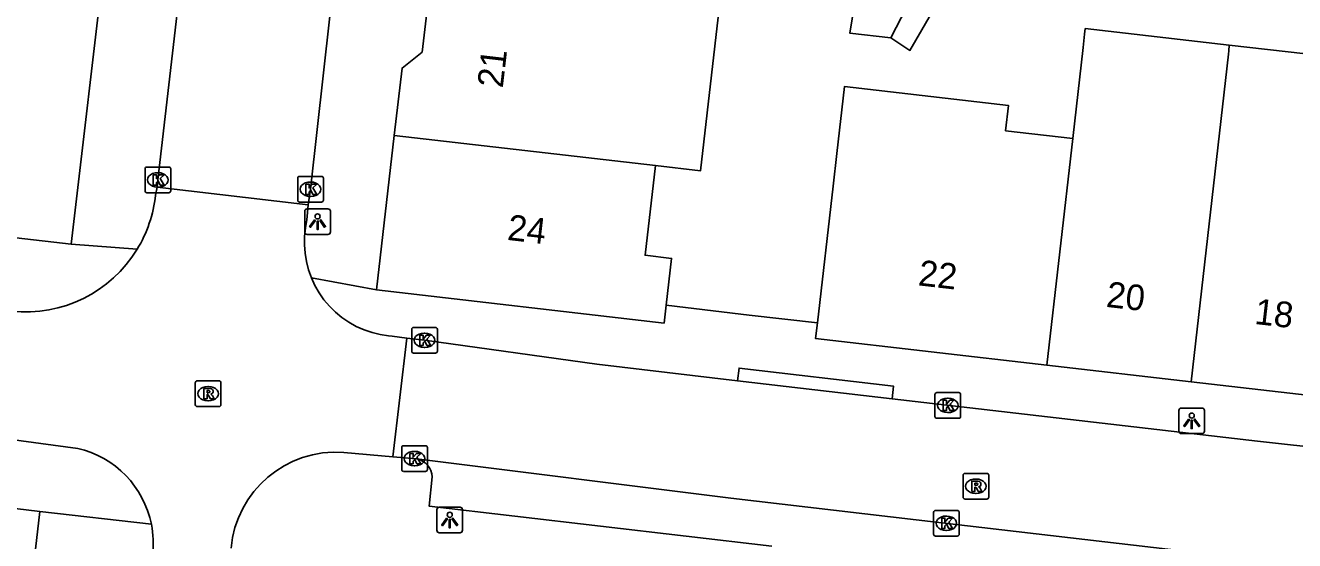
# Model space of a CAD drawing. Extents: x 161696 to 162377, y 380761 to 381673.
# Drawn here: x 162152.75 to 162202.16, y 381134.62 to 381154.7 of the extents above; entities that cross this region are included whole.
import ezdxf

# ---------------------------------------------------------------- set-up
doc = ezdxf.new("R2010")
doc.units = 0
for name, color, linetype in [('IMGEO_Kolk', 7, 'Continuous'), ('IMGEO_Lichtpunt', 7, 'Continuous'), ('IMGEO_Muur', 7, 'Continuous'), ('IMGEO_Pand', 7, 'Continuous'), ('IMGEO_Pand_nummerreeks', 7, 'Continuous'), ('IMGEO_Rijbaan_lokaal_open', 7, 'Continuous'), ('IMGEO_Rioolput', 7, 'Continuous'), ('IMGEO_Voetpad_open', 7, 'Continuous')]:
    doc.layers.add(name, color=color, linetype=linetype)

msp = doc.modelspace()

# ---------------------------------------------------------------- linework, layer by layer
at = {"layer": 'IMGEO_Kolk'}
for p, q in [((162157.405, 381148.25), (162157.405, 381149.102)), ((162157.48, 381149.176), (162158.332, 381149.176)), ((162157.893, 381148.956), (162157.918, 381148.956)), ((162158.406, 381149.102), (162158.406, 381148.25)), ((162163.424, 381148.812), (162164.276, 381148.812)), ((162157.916, 381148.396), (162157.891, 381148.396)), ((162163.349, 381147.886), (162163.349, 381148.738)), ((162163.837, 381148.592), (162163.862, 381148.592)), ((162164.35, 381148.738), (162164.35, 381147.886)), ((162158.332, 381148.176), (162157.48, 381148.176)), ((162164.276, 381147.812), (162163.424, 381147.812)), ((162163.86, 381148.032), (162163.835, 381148.032)), ((162167.787, 381142.001), (162167.787, 381142.853)), ((162167.862, 381142.927), (162168.714, 381142.927)), ((162168.788, 381142.853), (162168.788, 381142.001)), ((162168.275, 381142.707), (162168.3, 381142.707)), ((162168.714, 381141.927), (162167.862, 381141.927)), ((162168.298, 381142.147), (162168.273, 381142.147)), ((162188.234, 381140.39), (162189.086, 381140.39)), ((162188.159, 381139.464), (162188.159, 381140.316)), ((162188.647, 381140.17), (162188.672, 381140.17)), ((162189.16, 381140.316), (162189.16, 381139.464)), ((162189.086, 381139.39), (162188.234, 381139.39)), ((162188.67, 381139.61), (162188.645, 381139.61)), ((162167.399, 381137.393), (162167.399, 381138.245)), ((162167.474, 381138.319), (162168.326, 381138.319)), ((162167.887, 381138.099), (162167.912, 381138.099)), ((162168.4, 381138.245), (162168.4, 381137.393)), ((162167.91, 381137.539), (162167.885, 381137.539)), ((162168.326, 381137.319), (162167.474, 381137.319)), ((162188.103, 381134.872), (162188.103, 381135.724)), ((162188.178, 381135.798), (162189.03, 381135.798)), ((162188.591, 381135.578), (162188.616, 381135.578)), ((162189.104, 381135.724), (162189.104, 381134.872)), ((162188.614, 381135.018), (162188.589, 381135.018)), ((162189.03, 381134.798), (162188.178, 381134.798))]:
    msp.add_line(p, q, dxfattribs=at)
for points in [[(162157.405, 381148.25), (162157.405, 381149.102)], [(162157.48, 381149.176), (162158.332, 381149.176)], [(162157.726, 381148.876), (162157.849, 381148.876), (162157.849, 381148.725), (162157.979, 381148.876), (162158.143, 381148.876), (162157.997, 381148.725), (162158.15, 381148.476), (162157.998, 381148.476), (162157.913, 381148.64), (162157.849, 381148.573), (162157.849, 381148.476), (162157.726, 381148.476), (162157.726, 381148.876)], [(162158.406, 381149.102), (162158.406, 381148.25)], [(162163.424, 381148.812), (162164.276, 381148.812)], [(162163.349, 381147.886), (162163.349, 381148.738)], [(162163.67, 381148.512), (162163.793, 381148.512), (162163.793, 381148.361), (162163.923, 381148.512), (162164.087, 381148.512), (162163.941, 381148.361), (162164.094, 381148.112), (162163.942, 381148.112), (162163.857, 381148.276), (162163.793, 381148.209), (162163.793, 381148.112), (162163.67, 381148.112), (162163.67, 381148.512)], [(162164.35, 381148.738), (162164.35, 381147.886)], [(162158.332, 381148.176), (162157.48, 381148.176)], [(162164.276, 381147.812), (162163.424, 381147.812)], [(162167.787, 381142.001), (162167.787, 381142.853)], [(162167.862, 381142.927), (162168.714, 381142.927)], [(162168.788, 381142.853), (162168.788, 381142.001)], [(162168.108, 381142.627), (162168.231, 381142.627), (162168.231, 381142.476), (162168.361, 381142.627), (162168.525, 381142.627), (162168.379, 381142.476), (162168.532, 381142.227), (162168.38, 381142.227), (162168.295, 381142.391), (162168.231, 381142.324), (162168.231, 381142.227), (162168.108, 381142.227), (162168.108, 381142.627)], [(162168.714, 381141.927), (162167.862, 381141.927)], [(162188.234, 381140.39), (162189.086, 381140.39)], [(162188.159, 381139.464), (162188.159, 381140.316)], [(162188.48, 381140.09), (162188.603, 381140.09), (162188.603, 381139.939), (162188.733, 381140.09), (162188.897, 381140.09), (162188.751, 381139.939), (162188.904, 381139.69), (162188.752, 381139.69), (162188.667, 381139.854), (162188.603, 381139.787), (162188.603, 381139.69), (162188.48, 381139.69), (162188.48, 381140.09)], [(162189.16, 381140.316), (162189.16, 381139.464)], [(162189.086, 381139.39), (162188.234, 381139.39)], [(162167.399, 381137.393), (162167.399, 381138.245)], [(162167.474, 381138.319), (162168.326, 381138.319)], [(162167.72, 381138.019), (162167.843, 381138.019), (162167.843, 381137.868), (162167.973, 381138.019), (162168.137, 381138.019), (162167.991, 381137.868), (162168.144, 381137.619), (162167.992, 381137.619), (162167.907, 381137.783), (162167.843, 381137.716), (162167.843, 381137.619), (162167.72, 381137.619), (162167.72, 381138.019)], [(162168.4, 381138.245), (162168.4, 381137.393)], [(162168.326, 381137.319), (162167.474, 381137.319)], [(162188.103, 381134.872), (162188.103, 381135.724)], [(162188.178, 381135.798), (162189.03, 381135.798)], [(162188.424, 381135.498), (162188.547, 381135.498), (162188.547, 381135.347), (162188.677, 381135.498), (162188.841, 381135.498), (162188.695, 381135.347), (162188.848, 381135.098), (162188.696, 381135.098), (162188.611, 381135.262), (162188.547, 381135.195), (162188.547, 381135.098), (162188.424, 381135.098), (162188.424, 381135.498)], [(162189.104, 381135.724), (162189.104, 381134.872)], [(162189.03, 381134.798), (162188.178, 381134.798)]]:
    msp.add_lwpolyline(points, dxfattribs=at)
for centre, start, end in [((162157.482, 381149.1), 91.552, 178.448), ((162157.482, 381149.1), 91.552, 178.448), ((162158.33, 381149.1), 1.552, 88.448), ((162158.33, 381149.1), 1.552, 88.448), ((162163.426, 381148.736), 91.552, 178.448), ((162163.426, 381148.736), 91.552, 178.448), ((162164.274, 381148.736), 1.552, 88.448), ((162164.274, 381148.736), 1.552, 88.448), ((162157.482, 381148.252), 181.552, 268.448), ((162157.482, 381148.252), 181.552, 268.448), ((162158.33, 381148.252), 271.552, 358.448), ((162158.33, 381148.252), 271.552, 358.448), ((162163.426, 381147.888), 181.552, 268.448), ((162163.426, 381147.888), 181.552, 268.448), ((162164.274, 381147.888), 271.552, 358.448), ((162164.274, 381147.888), 271.552, 358.448), ((162167.864, 381142.851), 91.552, 178.448), ((162167.864, 381142.851), 91.552, 178.448), ((162168.712, 381142.851), 1.552, 88.448), ((162168.712, 381142.851), 1.552, 88.448), ((162167.864, 381142.003), 181.552, 268.448), ((162167.864, 381142.003), 181.552, 268.448), ((162168.712, 381142.003), 271.552, 358.448), ((162168.712, 381142.003), 271.552, 358.448), ((162188.236, 381140.314), 91.552, 178.448), ((162188.236, 381140.314), 91.552, 178.448), ((162189.084, 381140.314), 1.552, 88.448), ((162189.084, 381140.314), 1.552, 88.448), ((162188.236, 381139.466), 181.552, 268.448), ((162188.236, 381139.466), 181.552, 268.448), ((162189.084, 381139.466), 271.552, 358.448), ((162189.084, 381139.466), 271.552, 358.448), ((162167.476, 381138.243), 91.552, 178.448), ((162167.476, 381138.243), 91.552, 178.448), ((162168.324, 381138.243), 1.552, 88.448), ((162168.324, 381138.243), 1.552, 88.448), ((162167.476, 381137.395), 181.552, 268.448), ((162167.476, 381137.395), 181.552, 268.448), ((162168.324, 381137.395), 271.552, 358.448), ((162168.324, 381137.395), 271.552, 358.448), ((162188.18, 381135.722), 91.552, 178.448), ((162188.18, 381135.722), 91.552, 178.448), ((162189.028, 381135.722), 1.552, 88.448), ((162189.028, 381135.722), 1.552, 88.448), ((162188.18, 381134.874), 181.552, 268.448), ((162188.18, 381134.874), 181.552, 268.448), ((162189.028, 381134.874), 271.552, 358.448), ((162189.028, 381134.874), 271.552, 358.448)]:
    msp.add_arc(centre, 0.0765, start, end, dxfattribs=at)
for centre, major_axis, ratio, start_param, end_param in [((162157.892, 381148.676), (-0.387, 0.002), 0.722429, 4.712389, 7.853982), ((162157.917, 381148.676), (-0.39, 0.002), 0.717154, 1.570796, 4.712389), ((162163.836, 381148.312), (-0.387, 0.002), 0.722429, 4.712389, 7.853982), ((162163.861, 381148.312), (-0.39, 0.002), 0.717154, 1.570796, 4.712389), ((162168.274, 381142.427), (-0.387, 0.002), 0.722429, 4.712389, 7.853982), ((162168.299, 381142.427), (-0.39, 0.002), 0.717154, 1.570796, 4.712389), ((162188.646, 381139.89), (-0.387, 0.002), 0.722429, 4.712389, 7.853982), ((162188.671, 381139.89), (-0.39, 0.002), 0.717154, 1.570796, 4.712389), ((162167.886, 381137.819), (-0.387, 0.002), 0.722429, 4.712389, 7.853982), ((162167.911, 381137.819), (-0.39, 0.002), 0.717154, 1.570796, 4.712389), ((162188.59, 381135.298), (-0.387, 0.002), 0.722429, 4.712389, 7.853982), ((162188.615, 381135.298), (-0.39, 0.002), 0.717154, 1.570796, 4.712389)]:
    msp.add_ellipse(centre, major_axis=major_axis, ratio=ratio, start_param=start_param, end_param=end_param, dxfattribs=at)
at = {"layer": 'IMGEO_Lichtpunt'}
for p, q in [((162163.625, 381147.454), (162163.625, 381146.647)), ((162163.625, 381147.454), (162163.625, 381146.647)), ((162164.527, 381147.549), (162163.719, 381147.549)), ((162164.527, 381147.549), (162163.719, 381147.549)), ((162164.621, 381146.647), (162164.621, 381147.454)), ((162164.621, 381146.647), (162164.621, 381147.454)), ((162163.719, 381146.553), (162164.527, 381146.553)), ((162163.719, 381146.553), (162164.527, 381146.553)), ((162197.658, 381139.693), (162197.658, 381138.886)), ((162197.658, 381139.693), (162197.658, 381138.886)), ((162198.56, 381139.788), (162197.752, 381139.788)), ((162198.56, 381139.788), (162197.752, 381139.788)), ((162198.654, 381138.886), (162198.654, 381139.693)), ((162198.654, 381138.886), (162198.654, 381139.693)), ((162197.752, 381138.792), (162198.56, 381138.792)), ((162197.752, 381138.792), (162198.56, 381138.792)), ((162169.669, 381135.925), (162168.861, 381135.925)), ((162169.669, 381135.925), (162168.861, 381135.925)), ((162168.767, 381135.83), (162168.767, 381135.023)), ((162168.767, 381135.83), (162168.767, 381135.023)), ((162169.763, 381135.023), (162169.763, 381135.83)), ((162169.763, 381135.023), (162169.763, 381135.83)), ((162168.861, 381134.929), (162169.669, 381134.929)), ((162168.861, 381134.929), (162169.669, 381134.929))]:
    msp.add_line(p, q, dxfattribs=at)
for points in [[(162163.999, 381147.118), (162164.038, 381147.09), (162163.85, 381146.828), (162163.812, 381146.855), (162163.999, 381147.118)], [(162164.101, 381147.07), (162164.148, 381147.07), (162164.148, 381146.748), (162164.101, 381146.748), (162164.101, 381147.07)], [(162164.211, 381147.09), (162164.249, 381147.117), (162164.436, 381146.855), (162164.397, 381146.827), (162164.211, 381147.09)], [(162198.032, 381139.357), (162198.071, 381139.329), (162197.883, 381139.067), (162197.845, 381139.094), (162198.032, 381139.357)], [(162198.134, 381139.309), (162198.181, 381139.309), (162198.181, 381138.987), (162198.134, 381138.987), (162198.134, 381139.309)], [(162198.244, 381139.329), (162198.282, 381139.356), (162198.469, 381139.094), (162198.43, 381139.066), (162198.244, 381139.329)], [(162169.141, 381135.494), (162169.18, 381135.466), (162168.992, 381135.204), (162168.954, 381135.231), (162169.141, 381135.494)], [(162169.243, 381135.446), (162169.29, 381135.446), (162169.29, 381135.124), (162169.243, 381135.124), (162169.243, 381135.446)], [(162169.353, 381135.466), (162169.391, 381135.493), (162169.578, 381135.231), (162169.539, 381135.203), (162169.353, 381135.466)]]:
    msp.add_lwpolyline(points, dxfattribs=at)
for centre in [(162164.124, 381147.252), (162198.157, 381139.491), (162169.266, 381135.628)]:
    msp.add_circle(centre, 0.0994, dxfattribs=at)
for centre, start, end in [((162163.719, 381147.454), 90, 180), ((162163.719, 381147.454), 90, 180), ((162164.527, 381147.454), 0, 90), ((162164.527, 381147.454), 0, 90), ((162163.719, 381146.647), 180, 270), ((162163.719, 381146.647), 180, 270), ((162164.527, 381146.647), 270, 0), ((162164.527, 381146.647), 270, 360), ((162197.752, 381139.693), 90, 180), ((162197.752, 381139.693), 90, 180), ((162198.56, 381139.693), 0, 90), ((162198.56, 381139.693), 0, 90), ((162197.752, 381138.886), 180, 270), ((162197.752, 381138.886), 180, 270), ((162198.56, 381138.886), 270, 0), ((162198.56, 381138.886), 270, 360), ((162168.861, 381135.83), 90, 180), ((162168.861, 381135.83), 90, 180), ((162169.669, 381135.83), 0, 90), ((162169.669, 381135.83), 0, 90), ((162168.861, 381135.023), 180, 270), ((162168.861, 381135.023), 180, 270), ((162169.669, 381135.023), 270, 0), ((162169.669, 381135.023), 270, 360)]:
    msp.add_arc(centre, 0.0946, start, end, dxfattribs=at)
at = {"layer": 'IMGEO_Muur'}
msp.add_lwpolyline([(162177.694, 381143.796), (162180.605, 381143.446)], dxfattribs=at)
at = {"layer": 'IMGEO_Pand'}
for points in [[(162186.438, 381154.204), (162184.851, 381154.388), (162185.377, 381157.678), (162188.067, 381157.367)], [(162188.067, 381157.367), (162186.438, 381154.204)], [(162167.107, 381150.404), (162167.412, 381153.033), (162168.194, 381153.652), (162168.502, 381156.312)], [(162179.724, 381155.017), (162179.03, 381149.027), (162177.278, 381149.23)], [(162193.523, 381150.286), (162193.925, 381153.829), (162193.985, 381154.352), (162194.01, 381154.57), (162199.62, 381153.925)], [(162198.134, 381140.811), (162199.583, 381153.573), (162199.597, 381153.707), (162199.62, 381153.925)], [(162199.62, 381153.925), (162202.606, 381153.582), (162203.142, 381154.11), (162204.868, 381153.912), (162204.933, 381153.739), (162205.168, 381153.112)], [(162183.584, 381143.104), (162184.191, 381148.432), (162184.336, 381149.703), (162184.634, 381152.312), (162191.022, 381151.577), (162190.91, 381150.587), (162193.523, 381150.286)], [(162166.411, 381144.391), (162167.107, 381150.404)], [(162167.107, 381150.404), (162177.278, 381149.23)], [(162193.523, 381150.286), (162192.52, 381141.456)], [(162177.278, 381149.23), (162176.873, 381145.737), (162177.905, 381145.618), (162177.694, 381143.796)], [(162177.694, 381143.796), (162177.613, 381143.094), (162166.411, 381144.391)], [(162192.52, 381141.456), (162183.513, 381142.49), (162183.584, 381143.104)], [(162198.134, 381140.811), (162192.52, 381141.456)], [(162203.896, 381140.149), (162198.134, 381140.811)]]:
    msp.add_lwpolyline(points, dxfattribs=at)
at = {"layer": 'IMGEO_Rijbaan_lokaal_open'}
for points in [[(162157.877, 381148.391), (162157.908, 381148.676), (162159.365, 381161.363), (162161.049, 381175.536), (162162.665, 381189.882)], [(162167.521, 381180.59), (162165.836, 381166.11), (162163.848, 381148.312), (162163.756, 381147.701)], [(162157.811, 381148.076), (162157.877, 381148.391)], [(162163.756, 381147.701), (162157.877, 381148.391)], [(162163.756, 381147.701), (162163.71, 381147.125), (162163.647, 381146.802), (162163.613, 381146.474), (162163.608, 381146.145), (162163.633, 381145.816), (162163.687, 381145.491), (162163.769, 381145.173), (162163.88, 381144.862)], [(162163.88, 381144.862), (162164.018, 381144.563), (162164.183, 381144.278), (162164.372, 381144.008), (162164.584, 381143.757), (162164.819, 381143.525), (162165.072, 381143.315), (162165.344, 381143.129), (162165.631, 381142.968), (162165.932, 381142.833), (162166.243, 381142.725), (162166.563, 381142.646), (162166.888, 381142.595), (162167.021, 381142.583), (162167.592, 381142.51)], [(162167.053, 381137.885), (162167.592, 381142.51)], [(162167.592, 381142.51), (162168.285, 381142.426), (162174.995, 381141.497), (162180.474, 381140.85)], [(162186.489, 381140.14), (162180.474, 381140.85)], [(162186.489, 381140.14), (162200.716, 381138.494), (162203.646, 381138.166), (162217.018, 381136.75), (162220.241, 381136.371)], [(162151.612, 381138.643), (162154.785, 381138.216)], [(162165.142, 381138.059), (162167.053, 381137.885)], [(162167.974, 381137.811), (162167.053, 381137.885)], [(162219.35, 381131.833), (162212.969, 381132.576), (162202.92, 381133.625), (162201.233, 381133.817), (162189.43, 381135.203), (162180.206, 381136.281), (162167.974, 381137.811)]]:
    msp.add_lwpolyline(points, dxfattribs=at)
for centre, radius, start, end in [((162152.776, 381148.61), 5.063, 328.5832, 353.9437), ((162152.754, 381148.616), 5.085, 263.9214, 328.6629), ((162153.918, 381134.508), 3.808, 11.3713, 76.838), ((162164.846, 381133.959), 4.111, 85.865, 174.8588), ((162153.939, 381134.506), 3.787, 353.4744, 11.4626)]:
    msp.add_arc(centre, radius, start, end, dxfattribs=at)
at = {"layer": 'IMGEO_Rioolput'}
for p, q in [((162159.36, 381139.921), (162159.36, 381140.773)), ((162159.435, 381140.847), (162160.287, 381140.847)), ((162159.848, 381140.627), (162159.873, 381140.627)), ((162160.361, 381140.773), (162160.361, 381139.921)), ((162159.871, 381140.067), (162159.846, 381140.067)), ((162160.287, 381139.847), (162159.435, 381139.847)), ((162189.255, 381136.315), (162189.255, 381137.167)), ((162189.33, 381137.241), (162190.182, 381137.241)), ((162189.743, 381137.021), (162189.768, 381137.021)), ((162190.256, 381137.167), (162190.256, 381136.315)), ((162189.766, 381136.461), (162189.741, 381136.461)), ((162190.182, 381136.241), (162189.33, 381136.241))]:
    msp.add_line(p, q, dxfattribs=at)
for points in [[(162159.36, 381139.921), (162159.36, 381140.773)], [(162159.435, 381140.847), (162160.287, 381140.847)], [(162159.949, 381140.545), (162159.697, 381140.547), (162159.697, 381140.147)], [(162159.875, 381140.466), (162159.821, 381140.466), (162159.821, 381140.385)], [(162159.821, 381140.385), (162159.873, 381140.385)], [(162160.361, 381140.773), (162160.361, 381139.921)], [(162159.697, 381140.147), (162159.821, 381140.147), (162159.821, 381140.309), (162159.832, 381140.309)], [(162159.879, 381140.28), (162159.95, 381140.147), (162160.09, 381140.147), (162160.025, 381140.273)], [(162160.287, 381139.847), (162159.435, 381139.847)], [(162189.255, 381136.315), (162189.255, 381137.167)], [(162189.33, 381137.241), (162190.182, 381137.241)], [(162189.844, 381136.939), (162189.592, 381136.941), (162189.592, 381136.541)], [(162190.256, 381137.167), (162190.256, 381136.315)], [(162189.592, 381136.541), (162189.716, 381136.541), (162189.716, 381136.703), (162189.727, 381136.703)], [(162189.77, 381136.86), (162189.716, 381136.86), (162189.716, 381136.779)], [(162189.716, 381136.779), (162189.768, 381136.779)], [(162189.774, 381136.674), (162189.845, 381136.541), (162189.985, 381136.541), (162189.92, 381136.667)], [(162190.182, 381136.241), (162189.33, 381136.241)]]:
    msp.add_lwpolyline(points, dxfattribs=at)
for centre, radius, start, end in [((162159.437, 381140.771), 0.0765, 91.552, 178.448), ((162159.437, 381140.771), 0.0765, 91.552, 178.448), ((162159.857, 381140.574), 0.19, 274.7715, 282.9687), ((162159.881, 381140.37), 0.0964, 77.0061, 93.1865), ((162159.895, 381140.427), 0.0378, 276.6634, 79.6772), ((162159.948, 381140.435), 0.109, 350.3612, 89.416), ((162159.946, 381140.435), 0.112, 277.5842, 350.9817), ((162160.285, 381140.771), 0.0765, 1.552, 88.448), ((162160.285, 381140.771), 0.0765, 1.552, 88.448), ((162159.437, 381139.923), 0.0765, 181.552, 268.448), ((162159.437, 381139.923), 0.0765, 181.552, 268.448), ((162159.831, 381140.256), 0.0533, 26.0293, 88.6989), ((162159.93, 381140.22), 0.108, 29.5134, 73.7905), ((162160.285, 381139.923), 0.0765, 271.552, 358.448), ((162160.285, 381139.923), 0.0765, 271.552, 358.448), ((162189.332, 381137.165), 0.0765, 91.552, 178.448), ((162189.332, 381137.165), 0.0765, 91.552, 178.448), ((162189.843, 381136.829), 0.109, 350.3612, 89.416), ((162190.18, 381137.165), 0.0765, 1.552, 88.448), ((162190.18, 381137.165), 0.0765, 1.552, 88.448), ((162189.726, 381136.65), 0.0533, 26.0293, 88.6989), ((162189.752, 381136.968), 0.19, 274.7715, 282.9687), ((162189.776, 381136.764), 0.0964, 77.0061, 93.1865), ((162189.79, 381136.821), 0.0378, 276.6634, 79.6772), ((162189.841, 381136.829), 0.112, 277.5842, 350.9817), ((162189.825, 381136.614), 0.108, 29.5134, 73.7905), ((162189.332, 381136.317), 0.0765, 181.552, 268.448), ((162189.332, 381136.317), 0.0765, 181.552, 268.448), ((162190.18, 381136.317), 0.0765, 271.552, 358.448), ((162190.18, 381136.317), 0.0765, 271.552, 358.448)]:
    msp.add_arc(centre, radius, start, end, dxfattribs=at)
for centre, major_axis, ratio, start_param, end_param in [((162159.847, 381140.347), (-0.387, 0.002), 0.722429, 4.712389, 7.853982), ((162159.872, 381140.347), (-0.39, 0.002), 0.717154, 1.570796, 4.712389), ((162189.742, 381136.741), (-0.387, 0.002), 0.722429, 4.712389, 7.853982), ((162189.767, 381136.741), (-0.39, 0.002), 0.717154, 1.570796, 4.712389)]:
    msp.add_ellipse(centre, major_axis=major_axis, ratio=ratio, start_param=start_param, end_param=end_param, dxfattribs=at)
at = {"layer": 'IMGEO_Voetpad_open'}
for points in [[(162199.213, 381203.105), (162194.213, 381159.563), (162190.787, 381159.956), (162187.187, 381153.72), (162186.438, 381154.204)], [(162154.533, 381146.175), (162155.871, 381157.555)], [(162105.038, 381151.871), (162154.533, 381146.175)], [(162154.533, 381146.175), (162157.097, 381145.971)], [(162166.411, 381144.391), (162163.88, 381144.862)], [(162177.694, 381143.796), (162180.605, 381143.446), (162180.922, 381143.41), (162183.584, 381143.104)], [(162180.474, 381140.85), (162180.534, 381141.346), (162186.549, 381140.636), (162186.489, 381140.14)], [(162181.815, 381134.401), (162168.467, 381135.958), (162168.578, 381137.101)], [(162148.389, 381136.356), (162153.313, 381135.753)], [(162153.313, 381135.753), (162150.568, 381112.043)], [(162153.313, 381135.753), (162157.651, 381135.259)]]:
    msp.add_lwpolyline(points, dxfattribs=at)
msp.add_arc((162167.848, 381137.092), 0.73, 0.7176, 80.0583, dxfattribs=at)

# ---------------------------------------------------------------- texts
at = {"layer": 'IMGEO_Pand_nummerreeks'}
for s, rotation, p in [('21', 83.3996, (162171.331, 381152.232)), ('24', 353.3955, (162171.481, 381146.341)), ('22', 353.4511, (162187.48, 381144.57)), ('20', 353.4568, (162194.797, 381143.731)), ('18', 353.4454, (162200.575, 381143.067))]:
    msp.add_text(s, height=1, rotation=rotation, dxfattribs=at).set_placement(p)

doc.saveas('drawing.dxf')
